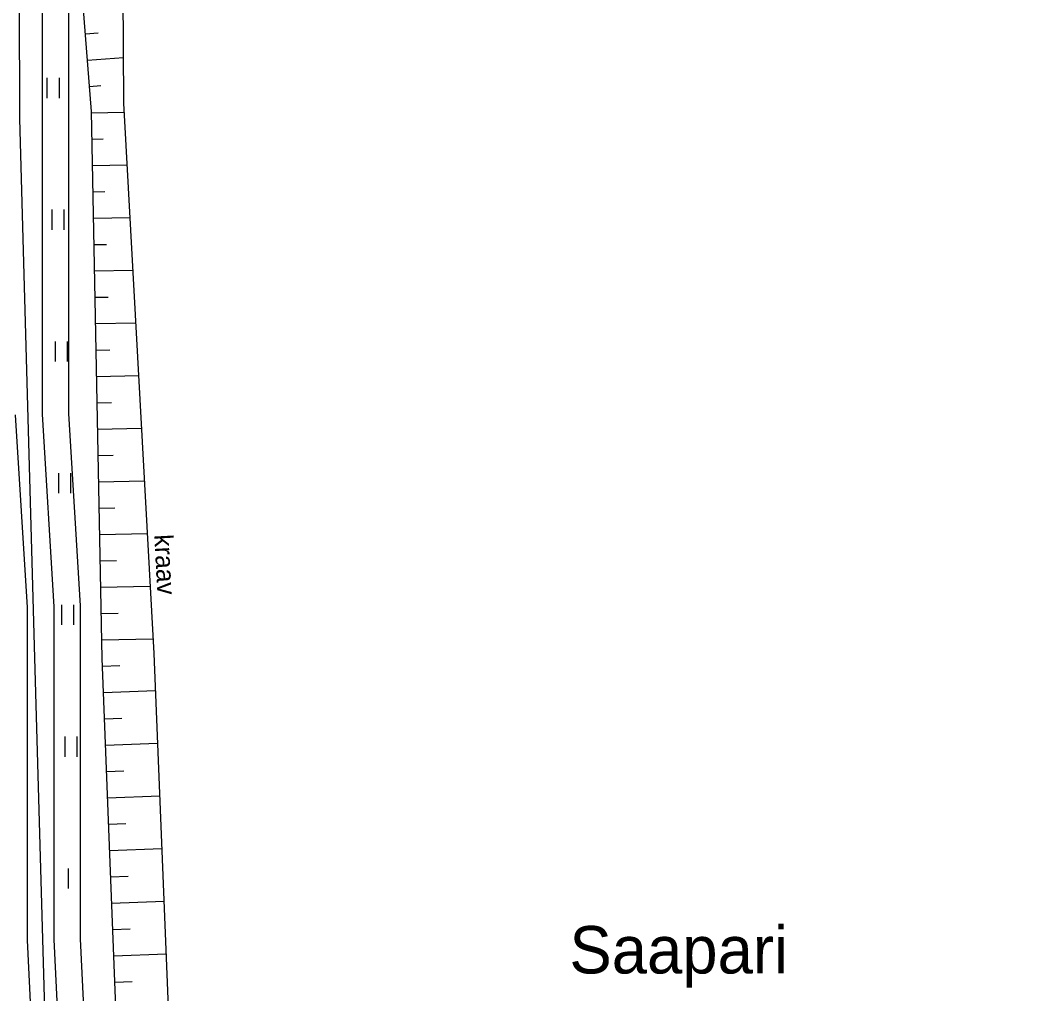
# Model space of a CAD drawing. Extents: x 657488 to 657645, y 6569018 to 6569240.
# Drawn here: x 657566.18 to 657604.79, y 6569129.03 to 6569165.96 of the extents above; entities that cross this region are included whole.
import ezdxf

# ---------------------------------------------------------------- set-up
doc = ezdxf.new("R2010")
doc.units = 0
for name, color, linetype in [('HALJASTUS', 7, 'Continuous'), ('KASUTUSALA', 7, 'Continuous'), ('PIIR', 7, 'Continuous'), ('PR_SIDE', 7, 'Continuous'), ('RELJEEF', 7, 'Continuous'), ('TEE', 7, 'Continuous'), ('VEEKOGU', 7, 'Continuous')]:
    doc.layers.add(name, color=color, linetype=linetype)

msp = doc.modelspace()

# ---------------------------------------------------------------- linework, layer by layer
at = {"layer": 'HALJASTUS'}
for p, q in [((657567.194, 6569163.771), (657567.194, 6569163.01)), ((657567.65, 6569163.771), (657567.65, 6569163.01)), ((657567.377, 6569158.775), (657567.377, 6569158.013)), ((657567.832, 6569158.775), (657567.832, 6569158.013)), ((657567.502, 6569153.776), (657567.502, 6569153.015)), ((657567.957, 6569153.776), (657567.957, 6569153.015)), ((657567.626, 6569148.778), (657567.626, 6569148.017)), ((657568.081, 6569148.778), (657568.081, 6569148.017)), ((657567.75, 6569143.779), (657567.75, 6569143.018)), ((657568.205, 6569143.779), (657568.205, 6569143.018)), ((657567.874, 6569138.781), (657567.874, 6569138.02)), ((657568.329, 6569138.781), (657568.329, 6569138.02)), ((657567.998, 6569133.782), (657567.998, 6569133.021)), ((657568.453, 6569133.782), (657568.453, 6569133.021))]:
    msp.add_line(p, q, dxfattribs=at)
at = {"layer": 'KASUTUSALA'}
for points in [[(657547.908, 6569185.316), (657566.447, 6569182.172), (657567.352, 6569182.019), (657585.5, 6569178.941), (657585.549, 6569179.455), (657588.033, 6569179.219), (657588.559, 6569179.496), (657591.709, 6569178.895), (657588.975, 6569177.455), (657588.82, 6569175.829), (657585.236, 6569176.17), (657585.31, 6569176.945), (657567.959, 6569179.887), (657567.787, 6569176.392), (657568.004, 6569171.419), (657568.004, 6569151.046), (657568.454, 6569143.738), (657568.454, 6569131.107), (657569.487, 6569109.777)], [(657567.489, 6569109.686), (657566.454, 6569131.059), (657566.454, 6569143.677), (657566.004, 6569150.984)]]:
    msp.add_lwpolyline(points, dxfattribs=at)
at = {"layer": 'PR_SIDE'}
msp.add_lwpolyline([(657567.085, 6569181.05), (657567.005, 6569180.843), (657566.787, 6569176.395), (657567.005, 6569171.398), (657567.005, 6569165.539), (657567.005, 6569158.584), (657567.005, 6569151.016), (657567.455, 6569143.708), (657567.455, 6569137.243), (657567.455, 6569131.084), (657568.489, 6569109.732), (657569.149, 6569094.452), (657569.149, 6569081.665), (657569.531, 6569068.343), (657563.3, 6569056.17)], dxfattribs=at)
at = {"layer": 'RELJEEF'}
for p, q in [((657568.649, 6569165.439), (657569.13, 6569165.477)), ((657568.728, 6569164.442), (657570.097, 6569164.55)), ((657568.806, 6569163.445), (657569.238, 6569163.479)), ((657568.881, 6569162.448), (657570.126, 6569162.472)), ((657568.9, 6569161.448), (657569.327, 6569161.457)), ((657568.92, 6569160.449), (657570.236, 6569160.474)), ((657568.939, 6569159.449), (657569.39, 6569159.457)), ((657568.958, 6569158.449), (657570.346, 6569158.476)), ((657568.978, 6569157.449), (657569.452, 6569157.458)), ((657568.997, 6569156.449), (657570.455, 6569156.478)), ((657569.016, 6569155.449), (657569.514, 6569155.459)), ((657569.036, 6569154.45), (657570.565, 6569154.479)), ((657569.055, 6569153.45), (657569.577, 6569153.46)), ((657569.075, 6569152.45), (657570.675, 6569152.481)), ((657569.094, 6569151.45), (657569.639, 6569151.461)), ((657569.113, 6569150.45), (657570.785, 6569150.483)), ((657569.133, 6569149.451), (657569.702, 6569149.462)), ((657569.152, 6569148.451), (657570.895, 6569148.485)), ((657569.171, 6569147.451), (657569.764, 6569147.462)), ((657569.191, 6569146.451), (657571.004, 6569146.486)), ((657569.21, 6569145.451), (657569.826, 6569145.463)), ((657569.229, 6569144.452), (657571.114, 6569144.488)), ((657569.249, 6569143.452), (657569.889, 6569143.464)), ((657569.268, 6569142.452), (657571.224, 6569142.49)), ((657569.293, 6569141.452), (657569.953, 6569141.478)), ((657569.332, 6569140.453), (657571.312, 6569140.531)), ((657569.372, 6569139.454), (657570.032, 6569139.48)), ((657569.411, 6569138.455), (657571.393, 6569138.532)), ((657569.45, 6569137.455), (657570.111, 6569137.481)), ((657569.489, 6569136.456), (657571.474, 6569136.534)), ((657569.528, 6569135.457), (657570.191, 6569135.483)), ((657569.568, 6569134.458), (657571.556, 6569134.536)), ((657569.607, 6569133.458), (657570.27, 6569133.484)), ((657569.646, 6569132.459), (657571.637, 6569132.537)), ((657569.685, 6569131.46), (657570.349, 6569131.486)), ((657569.724, 6569130.461), (657571.718, 6569130.539)), ((657569.763, 6569129.461), (657570.429, 6569129.488))]:
    msp.add_line(p, q, dxfattribs=at)
msp.add_lwpolyline([(657575.356, 6569071.541), (657575.057, 6569070.915), (657574.198, 6569070.482), (657573.247, 6569070.288), (657571.97, 6569070.573), (657571.429, 6569071.459), (657570.978, 6569085.148), (657570.566, 6569100.675), (657570.041, 6569122.388), (657569.282, 6569141.747), (657568.88, 6569162.504), (657567.502, 6569180.047), (657567.696, 6569183.905), (657568.878, 6569185.763), (657571.048, 6569186.396), (657579.979, 6569184.562), (657590.654, 6569181.999), (657604.789, 6569180.587)], dxfattribs=at)
at = {"layer": 'TEE'}
msp.add_lwpolyline([(657554.399, 6569061.998), (657559.246, 6569063.029), (657564.816, 6569064.832), (657569.624, 6569065.374), (657570.355, 6569067.363), (657568.529, 6569067.262), (657568.594, 6569069.383), (657568.421, 6569074.299), (657568.495, 6569085.242), (657567.806, 6569100.86), (657567.283, 6569122.208), (657566.728, 6569141.772), (657566.168, 6569162.215), (657566.107, 6569180.122), (657566.259, 6569183.437), (657568.587, 6569186.681), (657570.879, 6569187.829)], dxfattribs=at)
at = {"layer": 'VEEKOGU'}
msp.add_lwpolyline([(657574.071, 6569073.057), (657573.984, 6569072.504), (657573.232, 6569071.885), (657573.039, 6569072.48), (657572.681, 6569085.311), (657572.365, 6569101.179), (657572.042, 6569122.585), (657571.255, 6569141.933), (657570.107, 6569162.81), (657570.008, 6569179.615), (657570.443, 6569183.339), (657571.044, 6569183.413), (657571.785, 6569182.918), (657571.76, 6569181.994), (657571.427, 6569179.615), (657571.427, 6569175.989)], dxfattribs=at)

# ---------------------------------------------------------------- texts
at = {"layer": 'PIIR'}
msp.add_text('Saapari', height=1.8, dxfattribs=at).set_placement((657587.02, 6569129.796))
at = {"layer": 'VEEKOGU'}
msp.add_text('kraav', height=0.7, rotation=273.0999, dxfattribs=at).set_placement((657571.263, 6569146.436))

doc.saveas('drawing.dxf')
